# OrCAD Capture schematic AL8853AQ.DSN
size Custom; title: Automotive Compliant 40V Boost Controller; rev: 1.0; note: DS45623 Rev. 1-2
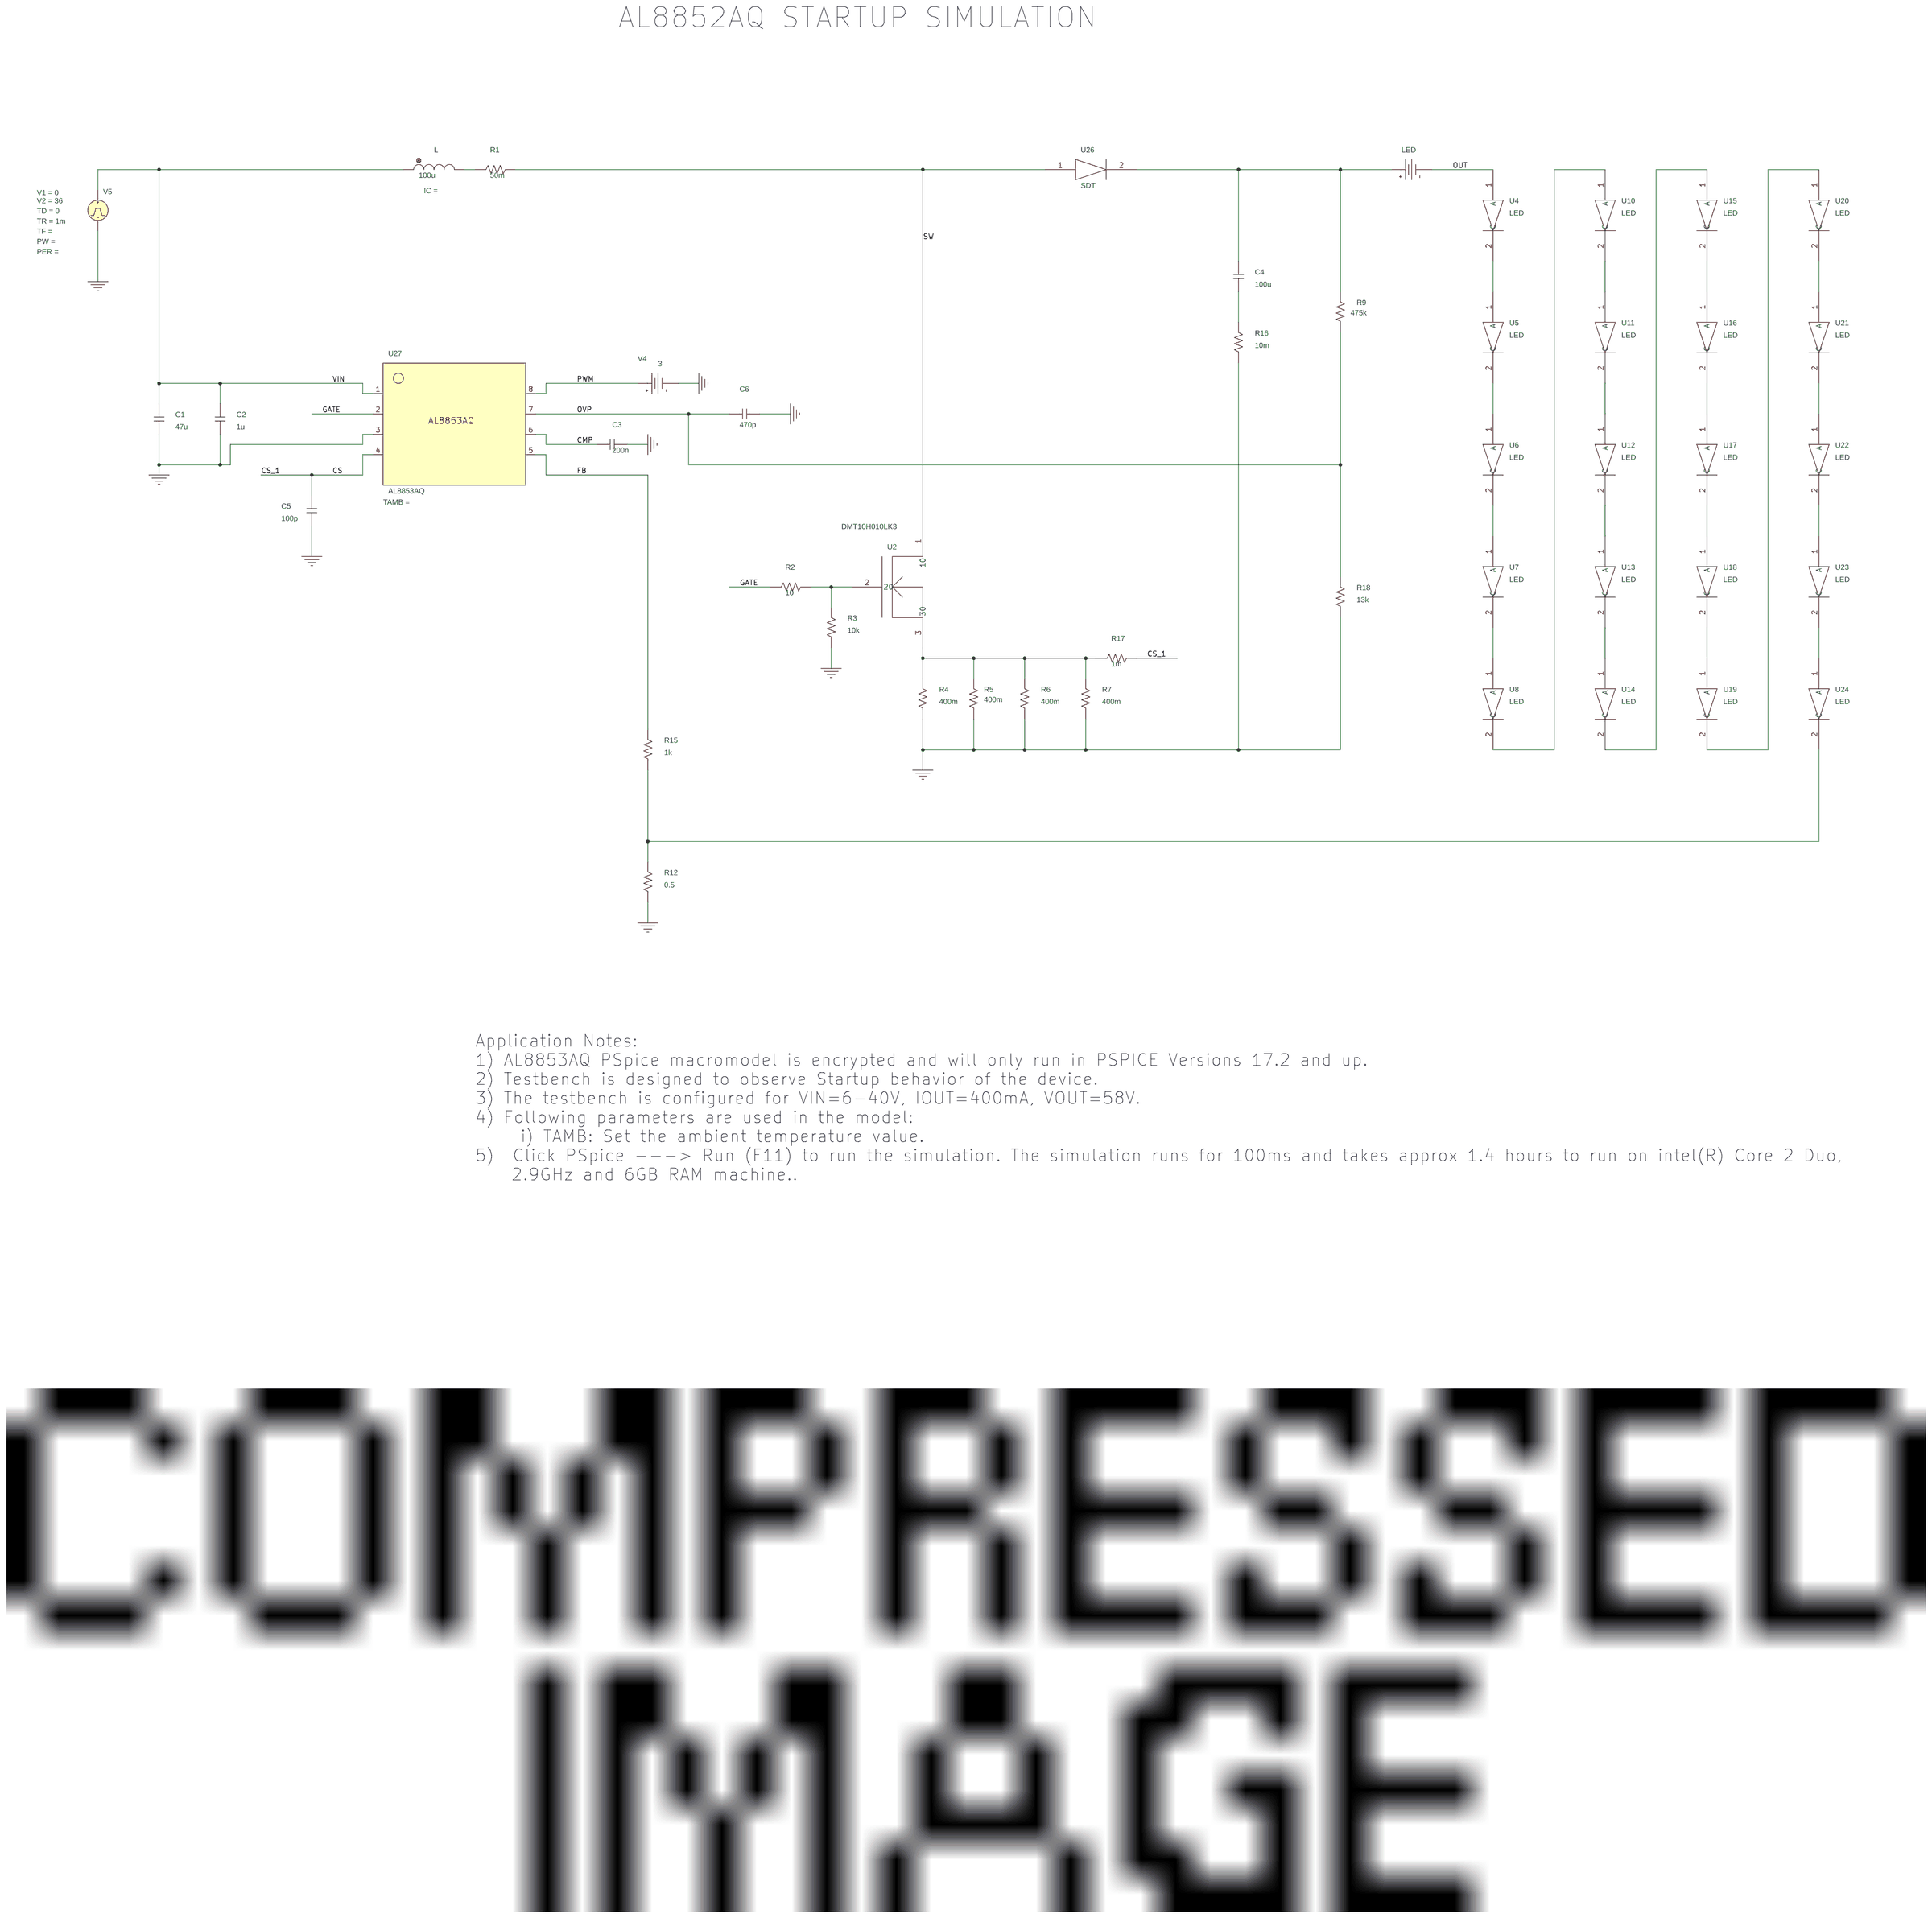
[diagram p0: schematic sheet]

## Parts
C1  47u  [RAD/CK05]
C2  1u  [RAD/CK05]
C3  200n  [RAD/CK05]
C4  100u  [RAD/CK05]
C5  100p  [RAD/CK05]
C6  470p  [RAD/CK05]
L  100u  [DISC/.350x.175/LS.200x.100/.034]
LED  VDC
R1  50m  [AX/RC05]
R2  10  [AX/RC05]
R3  10k  [AX/RC05]
R4  400m  [AX/RC05]
R5  400m  [AX/RC05]
R6  400m  [AX/RC05]
R7  400m  [AX/RC05]
R9  475k  [AX/RC05]
R12  0.5  [AX/RC05]
R15  1k  [AX/RC05]
R16  10m  [AX/RC05]
R17  1m  [AX/RC05]
R18  13k  [AX/RC05]
U2  DMT10H010LK3
U4  LED
U5  LED
U6  LED
U7  LED
U8  LED
U10  LED
U11  LED
U12  LED
U13  LED
U14  LED
U15  LED
U16  LED
U17  LED
U18  LED
U19  LED
U20  LED
U21  LED
U22  LED
U23  LED
U24  LED
U26  SDT
U27  AL8853AQ
V4  VDC
V5  VPULSE

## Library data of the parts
C1-C6 = C
L = L
LED = VDC
R1-R7 R9 R12 R15-R18 = R
U2 = DMT10H010LK3_0
U4-U8 U10-U24 = LED_0
U26 = SDT_0
U27 = AL8853AQ
V4 = VDC: DC: 3
V5 = VPULSE: TD: 0; TR: 1m; V1: 0; V2: 36

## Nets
VIN: C1.2 C2.2 L.1 U27.1(VIN) V5.1(+)
0: C1.1 C2.1 C3.2 C5.1 C6.1 R3.1 R4.1 R5.1 R6.1 R7.1 R12.1 R16.1 R18.1 U27.3(GND) V4.1(-) V5.2(-)
CMP: C3.1 U27.6(COMP)
CS: C5.2 R17.2 U27.4(CS)
FB: R15.2 U27.5(FB)
GATE: R2.1 U27.2(GATE)
OUT: LED.1(-) U4.1(A)
OVP: C6.2 R9.1 R18.2 U27.7(OVP)
PWM: U27.8(PWM) V4.0(+)
SW: R1.2 U2.1(10) U26.1
N16248095: L.2 R1.1
N16248125: C4.2 LED.0(+) R9.2 U26.2
N16248159: U8.2(C) U10.1(A)
N16248169: U14.2(C) U15.1(A)
N16248179: U19.2(C) U20.1(A)
N16248329: U4.2(C) U5.1(A)
N16248335: U10.2(C) U11.1(A)
N16248341: U15.2(C) U16.1(A)
N16248347: U20.2(C) U21.1(A)
N16248377: C4.1 R16.2
N16248635: U5.2(C) U6.1(A)
N16248641: U11.2(C) U12.1(A)
N16248647: U16.2(C) U17.1(A)
N16248653: U21.2(C) U22.1(A)
N16248971: U6.2(C) U7.1(A)
N16248977: U12.2(C) U13.1(A)
N16248983: U17.2(C) U18.1(A)
N16248989: U22.2(C) U23.1(A)
N16249153: R2.2 R3.2 U2.2(20)
N16249215: U7.2(C) U8.1(A)
N16249221: U13.2(C) U14.1(A)
N16249227: U18.2(C) U19.1(A)
N16249233: U23.2(C) U24.1(A)
N16249245: R4.2 R5.2 R6.2 R7.2 R17.1 U2.3(30)
N16249565: R12.2 R15.1 U24.2(C)

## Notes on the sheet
- AL8852AQ STARTUP SIMULATION
- Application Notes:
  1) AL8853AQ PSpice macromodel is encrypted and will only run in PSPICE Versions 17.2 and up.
  2) Testbench is designed to observe Startup behavior of the device.
  3) The testbench is configured for VIN=6-40V, IOUT=400mA, VOUT=58V.
  4) Following parameters are used in the model:
       i) TAMB: Set the ambient temperature value.
  5)  Click PSpice ---> Run (F11) to run the simulation. The simulation runs for 100ms and takes approx 1.4 hours to run on intel(R) Core 2 Duo,
      2.9GHz and 6GB RAM machine..
